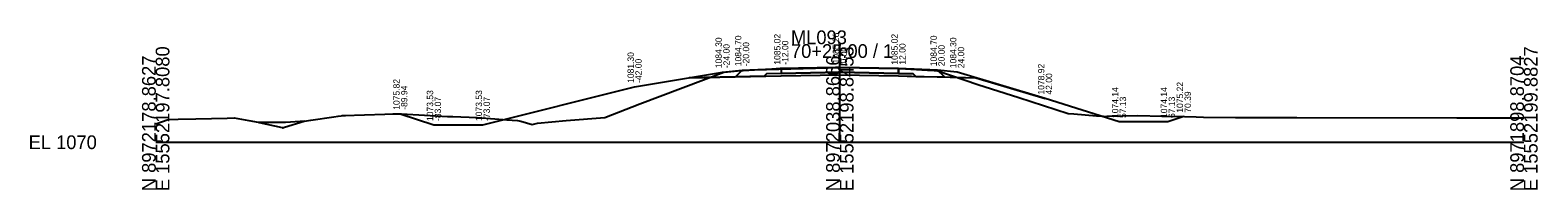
# Model space of a CAD drawing. Extents: x -26 to 14283, y -10 to 28.
# Drawn here: x 8974.3 to 9282.8, y -9.7 to 22.8 of the extents above; entities that cross this region are included whole.
import ezdxf

# ---------------------------------------------------------------- set-up
doc = ezdxf.new("R2010")
doc.units = 0
for name, color, linetype in [('Default', 7, 'Continuous'), ('dsn3DCenterLine', 7, 'Continuous'), ('dsn3DDitchBack', 7, 'Continuous'), ('dsn3DDitchFront', 7, 'Continuous'), ('dsn3DForeSlopeBarnRoofPoint', 7, 'Continuous'), ('dsn3DForeSlopeBreakLine', 7, 'Continuous'), ('dsn3DGroundLineIntercept', 7, 'Continuous'), ('dsn3DPavementTop', 7, 'Continuous'), ('dsn3DShoulderTop', 7, 'Continuous'), ('dsn3DSubgradeBreakLine', 7, 'Continuous'), ('dsn3DSubgradeHingePoint', 7, 'Continuous'), ('dsnGeopakCellCrossSection', 7, 'Continuous'), ('dsnXSEarthwork', 7, 'Continuous'), ('dsnXsExistingGround', 7, 'Continuous'), ('dsnXsPCCPavement', 7, 'Continuous'), ('dsnXsShldrEarthFill', 7, 'Continuous'), ('dsnXsShldrGranular', 7, 'Continuous'), ('dsnXsSideSlopes', 7, 'Continuous'), ('dsnXsSubbase', 7, 'Continuous'), ('dsnXsTextOffsetElevFinGrd', 7, 'Continuous'), ('SurBreakLine', 7, 'Continuous'), ('SurSurveyPoints', 7, 'Continuous')]:
    doc.layers.add(name, color=color, linetype=linetype)

msp = doc.modelspace()

# ---------------------------------------------------------------- linework, layer by layer
at = {"layer": 'Default'}
for points in [[(9109.16, 13.16), (9109.16, 13.16), (9128, 13.52), (9140, 13.76), (9152, 13.52), (9167.81, 13.16), (9182, 8.92)], [(9120, 14.7), (9140, 15.26), (9152, 15.02), (9160, 14.7)]]:
    msp.add_lwpolyline(points, dxfattribs=at)
at = {"layer": 'dsnGeopakCellCrossSection'}
for p, q in [((9140, 0), (9140, 20)), ((9000, 0), (9140, 0)), ((9140, 0), (9280, 0))]:
    msp.add_line(p, q, dxfattribs=at)
at = {"layer": 'dsnXSEarthwork'}
msp.add_lwpolyline([(9120, 14.7), (9128, 15.02), (9140, 15.26), (9152, 15.02), (9160, 14.7)], dxfattribs=at)
at = {"layer": 'dsnXsExistingGround'}
msp.add_lwpolyline([(9000, 3.74), (9002.52, 4.62), (9004.57, 4.68), (9008.19, 4.75), (9014.62, 4.94), (9016.09, 5), (9019.04, 4.4), (9020.97, 4.07), (9021.04, 4.06), (9021.16, 4.04), (9025.9, 3.03), (9026.38, 3.06), (9030.38, 4.27), (9031.74, 4.53), (9036.45, 5.16), (9037.34, 5.3), (9038.58, 5.47), (9046.89, 5.71), (9048.55, 5.76), (9049.32, 5.8), (9049.86, 5.82), (9050.29, 5.82), (9059.74, 5.26), (9060.79, 5.26), (9065.78, 5.04), (9069.42, 4.76), (9071.84, 4.59), (9074.05, 4.43), (9074.69, 4.28), (9077.04, 3.61), (9078.1, 3.87), (9084, 4.4), (9091.94, 5.04), (9099.04, 7.84), (9116.25, 14.3), (9117.04, 14.37), (9119.05, 14.55), (9126.09, 14.97), (9127.79, 15.08), (9139.14, 15.31), (9139.95, 15.33), (9151.17, 15.09), (9151.88, 15.07), (9152.29, 15.05), (9157.92, 14.71), (9158.46, 14.67), (9160.06, 14.56), (9168.27, 11.79), (9176.63, 9.12), (9186.72, 5.88), (9187.86, 5.8), (9192.49, 5.41), (9193.86, 5.3), (9194.11, 5.28), (9194.62, 5.3), (9200.98, 5.47), (9205.96, 5.34), (9210.5, 5.22), (9212.92, 5.15), (9214.43, 5.11), (9221, 5.03), (9233.49, 5.04), (9266.24, 4.98), (9280, 4.96)], dxfattribs=at)
at = {"layer": 'dsnXsPCCPavement'}
msp.add_lwpolyline([(9128, 15.02), (9128, 15.02), (9128, 14.02), (9128, 14.02), (9128, 14.02), (9140, 14.26), (9152, 14.02), (9152, 14.02), (9152, 14.02), (9152, 15.02), (9152, 15.02), (9140, 15.26), (9128, 15.02)], dxfattribs=at)
at = {"layer": 'dsnXsShldrEarthFill'}
for points in [[(9118.64, 13.34), (9109.16, 13.16)], [(9161.39, 13.31), (9167.81, 13.16)]]:
    msp.add_lwpolyline(points, dxfattribs=at)
at = {"layer": 'dsnXsShldrGranular'}
for points in [[(9120, 14.7), (9128, 15.02), (9128, 14.02), (9128, 14.02), (9125, 13.96), (9125, 13.96), (9124.49, 13.45), (9124.49, 13.45), (9118.64, 13.34), (9118.64, 13.34), (9118.64, 13.34), (9120, 14.7), (9120, 14.7)], [(9160, 14.7), (9152, 15.02), (9152, 14.02), (9152, 14.02), (9155, 13.96), (9155, 13.96), (9155.52, 13.44), (9155.52, 13.44), (9161.39, 13.31), (9161.39, 13.31), (9161.39, 13.31), (9160, 14.7), (9160, 14.7)]]:
    msp.add_lwpolyline(points, dxfattribs=at)
at = {"layer": 'dsnXsSideSlopes'}
for points in [[(9050.06, 5.82), (9056.93, 3.53), (9056.93, 3.53), (9066.93, 3.53), (9066.93, 3.53), (9098, 11.3), (9098, 11.3), (9098, 11.3), (9116, 14.3), (9116, 14.3), (9120, 14.7)], [(9210.39, 5.22), (9207.13, 4.14), (9207.13, 4.14), (9197.13, 4.14), (9197.13, 4.14), (9182, 8.92), (9182, 8.92), (9182, 8.92), (9164, 14.3), (9164, 14.3), (9160, 14.7)]]:
    msp.add_lwpolyline(points, dxfattribs=at)
at = {"layer": 'dsnXsSubbase'}
msp.add_lwpolyline([(9124.49, 13.45), (9124.49, 13.45), (9124.49, 13.45), (9128, 13.52), (9128, 13.52), (9140, 13.76), (9152, 13.52), (9152, 13.52), (9155.52, 13.44), (9155.52, 13.44), (9155.52, 13.44), (9155, 13.96), (9155, 13.96), (9152, 14.02), (9152, 14.02), (9140, 14.26), (9128, 14.02), (9128, 14.02), (9125, 13.96), (9125, 13.96), (9124.49, 13.45)], dxfattribs=at)
at = {"layer": 'SurBreakLine'}
msp.add_lwpolyline([(9030.38, 4.27), (9029.58, 4.22), (9026.54, 4.02), (9021.16, 4.04)], dxfattribs=at)
at = {"layer": 'SurSurveyPoints'}
for points in [[(9038.07, 5.48), (9038.84, 5.48)], [(9026.13, 2.85), (9025.92, 2.85)]]:
    msp.add_lwpolyline(points, dxfattribs=at)

# ---------------------------------------------------------------- texts
msp.add_text('-', height=0.0001).set_placement((9000, 0))
at = {"layer": 'dsn3DCenterLine'}
msp.add_text('X', height=0.00781, dxfattribs=at).set_placement((9140, 15.26))
at = {"layer": 'dsn3DDitchBack'}
for p in [(9056.92, 3.53), (9207.13, 4.13)]:
    msp.add_text('X', height=0.00781, dxfattribs=at).set_placement(p)
at = {"layer": 'dsn3DDitchFront'}
for p in [(9066.92, 3.53), (9197.13, 4.13)]:
    msp.add_text('X', height=0.00781, dxfattribs=at).set_placement(p)
at = {"layer": 'dsn3DForeSlopeBarnRoofPoint'}
for p in [(9098, 11.29), (9182, 8.92)]:
    msp.add_text('X', height=0.00781, dxfattribs=at).set_placement(p)
at = {"layer": 'dsn3DForeSlopeBreakLine'}
for p in [(9116, 14.3), (9164, 14.3)]:
    msp.add_text('X', height=0.00781, dxfattribs=at).set_placement(p)
at = {"layer": 'dsn3DGroundLineIntercept'}
for p in [(9050.06, 5.81), (9210.38, 5.22)]:
    msp.add_text('X', height=0.00781, dxfattribs=at).set_placement(p)
at = {"layer": 'dsn3DPavementTop'}
for p in [(9128, 15.02), (9152, 15.02)]:
    msp.add_text('X', height=0.00781, dxfattribs=at).set_placement(p)
at = {"layer": 'dsn3DShoulderTop'}
for p in [(9120, 14.7), (9160, 14.7)]:
    msp.add_text('X', height=0.00781, dxfattribs=at).set_placement(p)
at = {"layer": 'dsn3DSubgradeBreakLine'}
for p in [(9128, 13.52), (9140, 13.76), (9152, 13.52)]:
    msp.add_text('X', height=0.00781, dxfattribs=at).set_placement(p)
at = {"layer": 'dsn3DSubgradeHingePoint'}
for p in [(9109.16, 13.16), (9167.81, 13.16)]:
    msp.add_text('X', height=0.00781, dxfattribs=at).set_placement(p)
at = {"layer": 'dsnGeopakCellCrossSection'}
for s, p in [('ML093', (9130, 20)), ('70+25.00 / 1', (9130, 17.2)), ('EL 1070', (8974, -1.4))]:
    msp.add_text(s, height=2.8, dxfattribs=at).set_placement(p)
for s, p in [('E 15552197.8080', (9002.8, -10)), ('E 15552198.8453', (9142.8, -10)), ('E 15552199.8827', (9282.8, -10)), ('N 8972178.8627', (9000, -10)), ('N 8972038.8666', (9140, -10)), ('N 8971898.8704', (9280, -10))]:
    msp.add_text(s, height=2.8, rotation=90, dxfattribs=at).set_placement(p)
at = {"layer": 'dsnXsTextOffsetElevFinGrd'}
for s, p in [('1084.70', (9119.85, 15.5)), ('1085.02', (9127.85, 15.82)), ('1085.26', (9139.85, 16.06)), ('1085.02', (9151.85, 15.82)), ('1084.70', (9159.85, 15.5)), ('1084.30', (9115.85, 15.1)), ('1084.30', (9115.85, 15.1)), ('-24.00', (9117.45, 15.1)), ('-24.00', (9117.45, 15.1)), ('-20.00', (9121.45, 15.5)), ('-12.00', (9129.45, 15.82)), ('0.00', (9141.45, 16.06)), ('12.00', (9153.45, 15.82)), ('20.00', (9161.45, 15.5)), ('1084.30', (9163.85, 15.1)), ('24.00', (9165.45, 15.1)), ('1081.30', (9097.85, 12.1)), ('-42.00', (9099.45, 12.1)), ('1078.92', (9181.85, 9.72)), ('1075.82', (9049.91, 6.62)), ('42.00', (9183.45, 9.72)), ('-89.94', (9051.51, 6.62)), ('1073.53', (9056.78, 4.33)), ('1073.53', (9066.78, 4.33)), ('1074.14', (9196.98, 4.94)), ('1074.14', (9206.98, 4.94)), ('1075.22', (9210.24, 6.02)), ('1075.22', (9210.24, 6.02)), ('70.39', (9211.84, 6.02)), ('70.39', (9211.84, 6.02)), ('-83.07', (9058.38, 4.33)), ('-73.07', (9068.38, 4.33)), ('57.13', (9198.58, 4.94)), ('67.13', (9208.58, 4.94))]:
    msp.add_text(s, height=1.3, rotation=90, dxfattribs=at).set_placement(p)

doc.saveas('drawing.dxf')
